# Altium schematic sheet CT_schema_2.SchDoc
size 403 x 258 mm
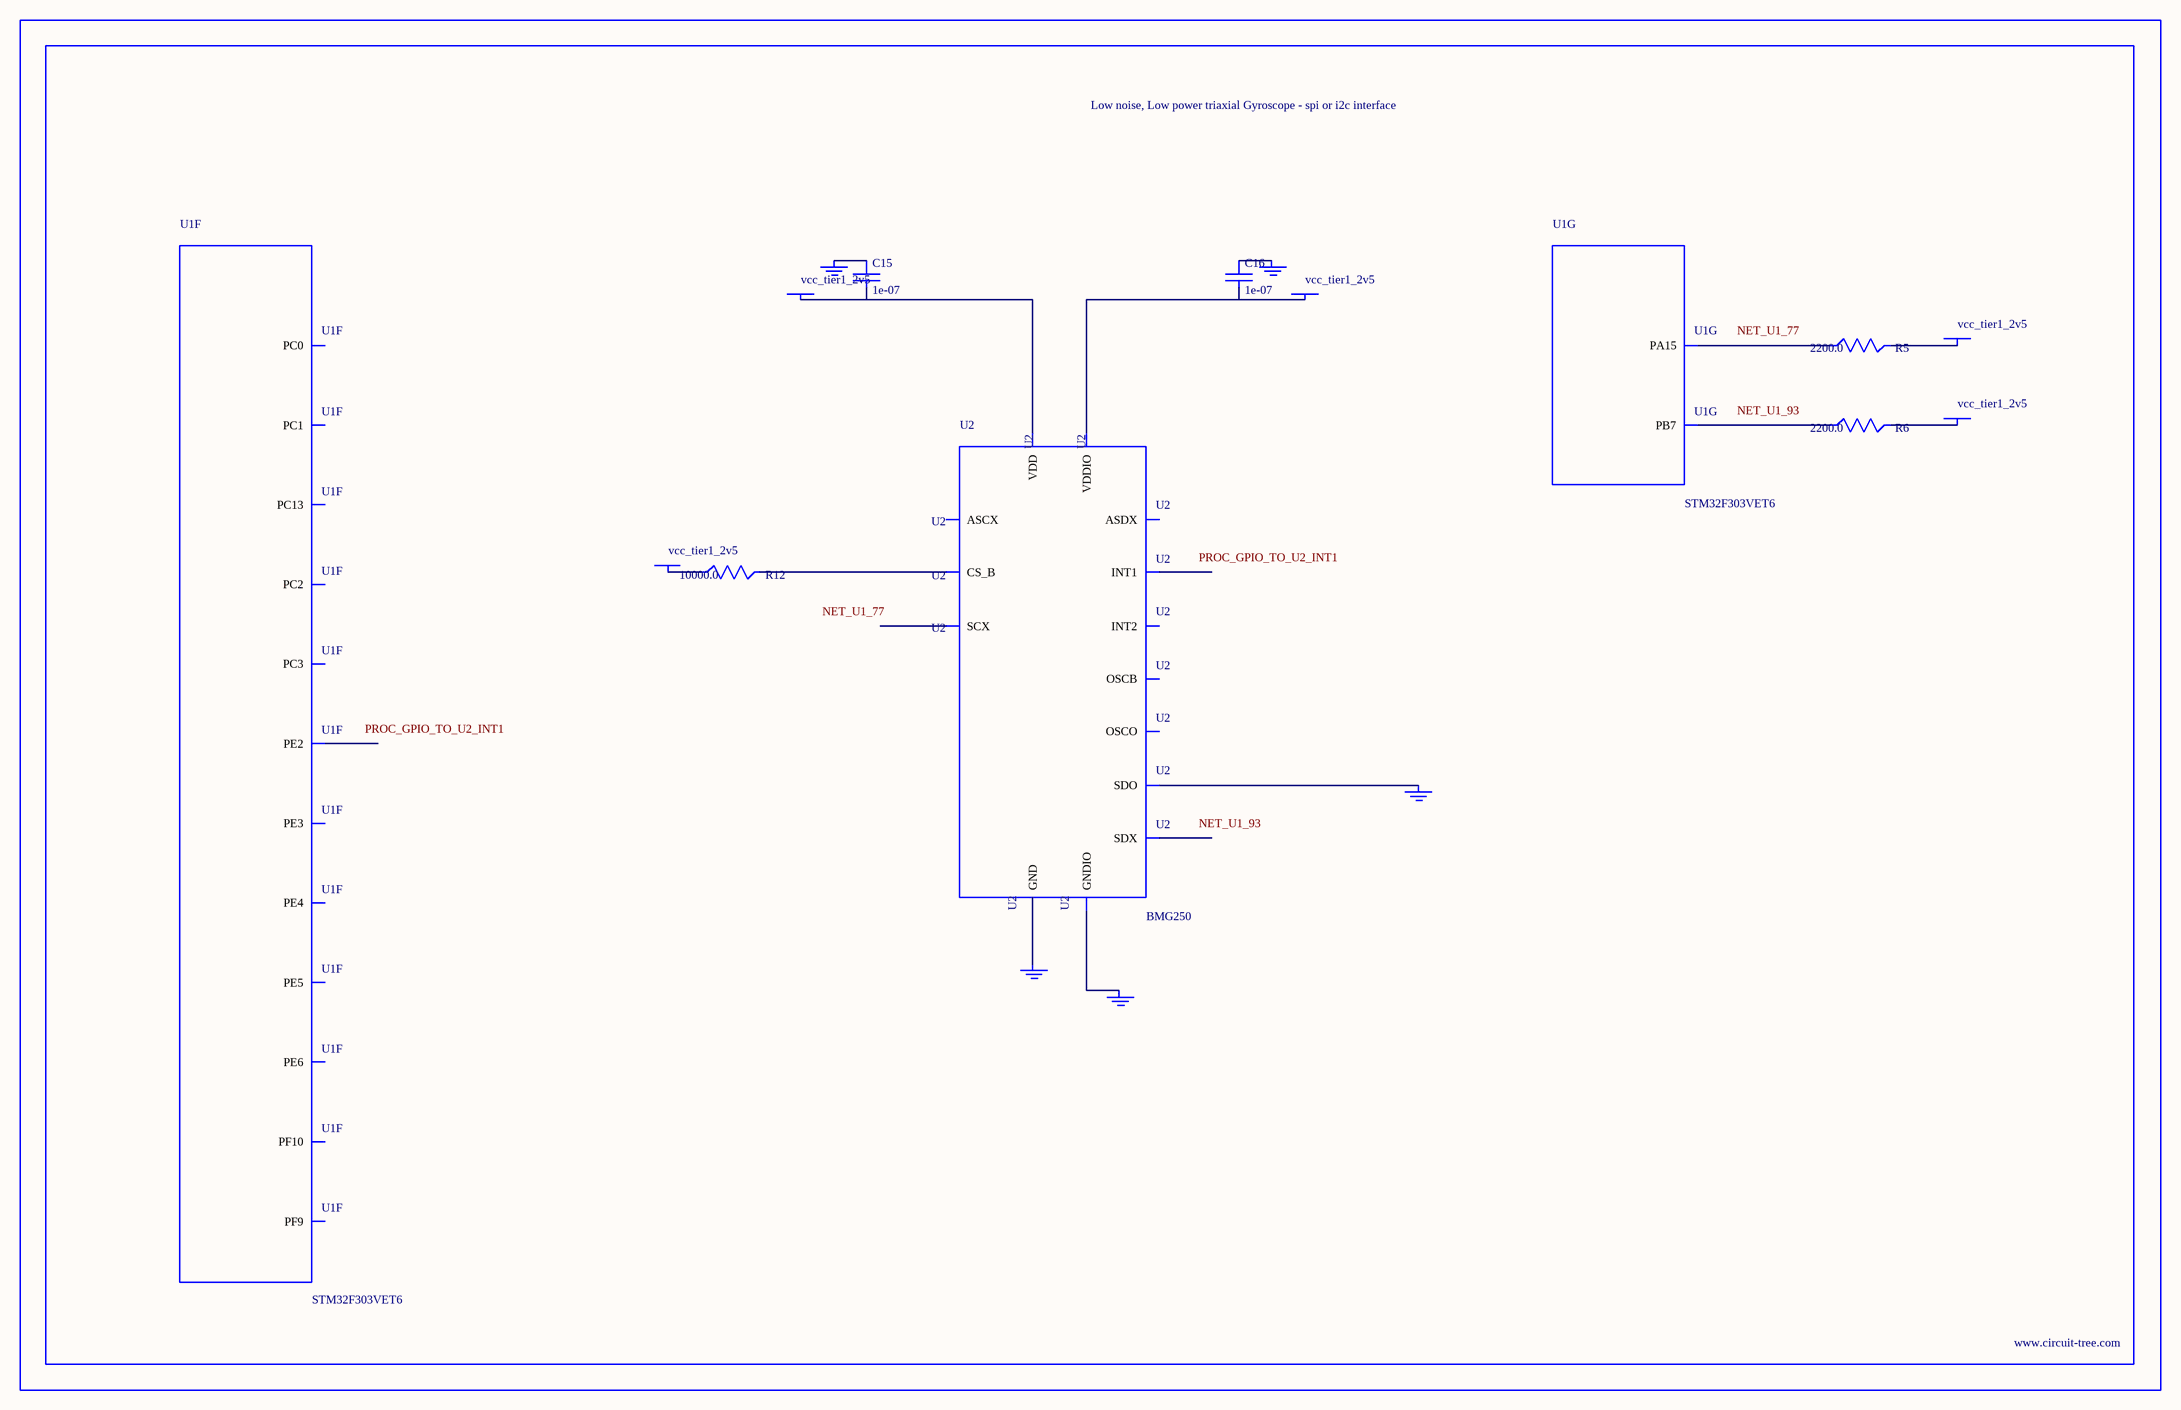
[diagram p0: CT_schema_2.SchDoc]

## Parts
BORDER1  (no value)
C15  1e-07  [C0402]
C16  1e-07  [C0402]
GND_INSTANCE_1_0  (no value)
GND_INSTANCE_1_1  (no value)
GND_INSTANCE_1_2  (no value)
GND_INSTANCE_1_3  (no value)
GND_INSTANCE_1_4  (no value)
POWER_INSTANCE_1_0  vcc_tier1_2v5
POWER_INSTANCE_1_1  vcc_tier1_2v5
POWER_INSTANCE_1_2  vcc_tier1_2v5
POWER_INSTANCE_1_3  vcc_tier1_2v5
POWER_INSTANCE_1_4  vcc_tier1_2v5
R5  2200.0  [R0603]
R6  2200.0  [R0603]
R12  10000.0  [R0603]
U1  STM32F303VET6  [LQFP100]  (parts F,G of 9)
U2  BMG250  [LGA-14]

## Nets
NetC15_1: C15.1 GND_INSTANCE_1_3.0(GND)
NetC15_2: C15.2 POWER_INSTANCE_1_1.0(PWR) U2.8(VDD)
NetC16_1: C16.1 GND_INSTANCE_1_1.0(GND)
NetC16_2: C16.2 POWER_INSTANCE_1_0.0(PWR) U2.5(VDDIO)
NetGND_INSTANCE_1_0_0: GND_INSTANCE_1_0.0(GND) U2.1(SDO)
NetGND_INSTANCE_1_2_0: GND_INSTANCE_1_2.0(GND) U2.6(GNDIO)
NetGND_INSTANCE_1_4_0: GND_INSTANCE_1_4.0(GND) U2.7(GND)
NetPOWER_INSTANCE_1_2_0: POWER_INSTANCE_1_2.0(PWR) R12.1
NetPOWER_INSTANCE_1_3_0: POWER_INSTANCE_1_3.0(PWR) R5.2
NetPOWER_INSTANCE_1_4_0: POWER_INSTANCE_1_4.0(PWR) R6.2
NetR5_1: R5.1 U1.77(PA15)
NetR6_1: R6.1 U1.93(PB7)
NetR12_2: R12.2 U2.12(CS_B)

Not connected (* = marked no-connect by the designer): U1 1(PE2) 2(PE3) 3(PE4) 4(PE5) 5(PE6) 7(PC13) 10(PF9) 11(PF10) 15(PC0) 16(PC1) 17(PC2) 18(PC3); U2 2(ASDX) 3(ASCX) 4(INT1) 9(INT2) 10(OSCB) 11(OSCO) 13(SCX) 14(SDX)

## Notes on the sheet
- Labels drawn without touching a wire or pin: NET_U1_77, NET_U1_93, PROC_GPIO_TO_U2_INT1

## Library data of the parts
BORDER1 = BORDER_PAGE1
C15 C16 = C0402C104K3RACTU
GND_INSTANCE_1_0-GND_INSTANCE_1_4 = GND
POWER_INSTANCE_1_0-POWER_INSTANCE_1_4 = PWR
R5 R6 = RC0603JR-072K2L
R12 = RC0603JR-0710KL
